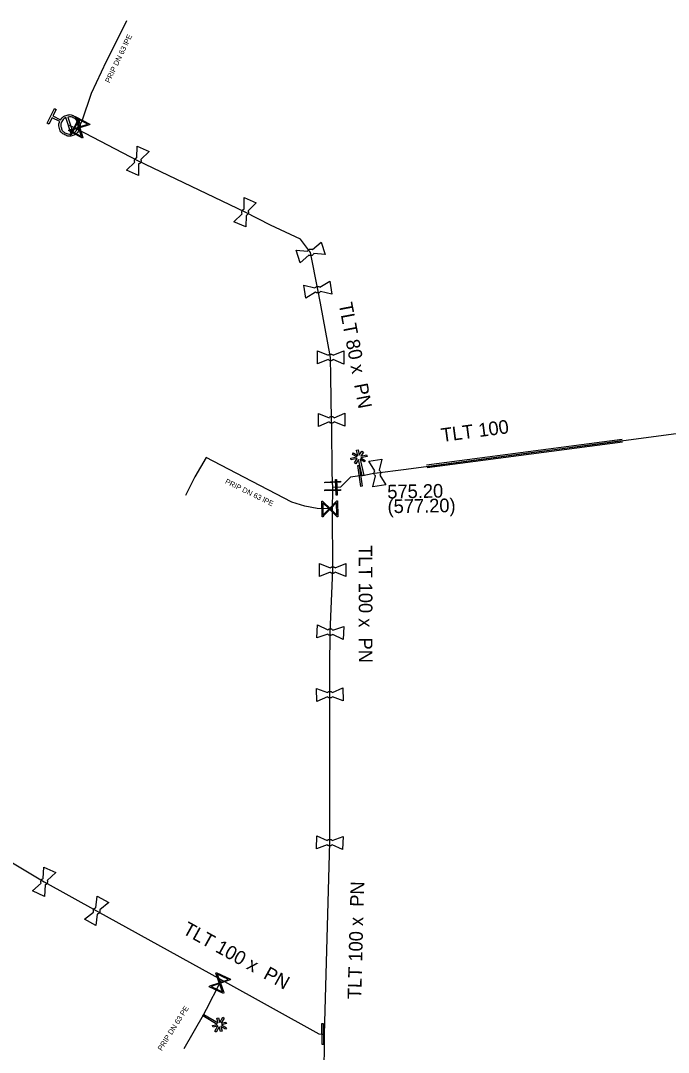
# Model space of a CAD drawing. Extents: x -643842 to -636370, y -1119190 to -1110210.
# Drawn here: x -641967.7 to -641906.1, y -1115301.5 to -1115203.3 of the extents above; entities that cross this region are included whole.
import ezdxf

# ---------------------------------------------------------------- set-up
doc = ezdxf.new("R2010")
doc.units = 0
for name, color, linetype in [('2', 7, 'Continuous'), ('22', 7, 'Continuous'), ('Default', 7, 'Continuous'), ('Level 16', 7, 'Continuous'), ('Level 20', 7, 'Continuous'), ('Level 21', 7, 'Continuous'), ('Level 23', 7, 'Continuous'), ('Level 27', 7, 'Continuous'), ('Level 28', 7, 'Continuous'), ('Level 29', 7, 'Continuous'), ('Level 30', 7, 'Continuous'), ('Level 33', 7, 'Continuous')]:
    doc.layers.add(name, color=color, linetype=linetype)

msp = doc.modelspace()

# ---------------------------------------------------------------- linework, layer by layer
at = {"layer": '2'}
for points in [[(-641935.602, -1115244.661), (-641935.717, -1115244.134), (-641935.565, -1115244.1), (-641935.451, -1115244.623), (-641935.198, -1115244.228), (-641935.067, -1115244.313), (-641935.318, -1115244.705), (-641934.755, -1115244.582), (-641934.721, -1115244.735), (-641935.294, -1115244.86), (-641934.895, -1115245.115), (-641934.978, -1115245.246), (-641935.369, -1115244.996), (-641935.031, -1115246.543), (-641935.184, -1115246.576), (-641935.523, -1115245.025), (-641935.777, -1115245.422), (-641935.908, -1115245.337), (-641935.653, -1115244.938), (-641936.224, -1115245.063), (-641936.257, -1115244.91), (-641935.696, -1115244.787), (-641936.085, -1115244.536), (-641936.002, -1115244.406), (-641935.602, -1115244.661)], [(-641948.558, -1115298.841), (-641948.091, -1115299.112), (-641948.17, -1115299.247), (-641948.632, -1115298.978), (-641948.512, -1115299.431), (-641948.663, -1115299.47), (-641948.782, -1115299.021), (-641949.072, -1115299.519), (-641949.207, -1115299.44), (-641948.913, -1115298.934), (-641949.37, -1115299.056), (-641949.41, -1115298.905), (-641948.962, -1115298.786), (-641950.331, -1115297.99), (-641950.252, -1115297.855), (-641948.879, -1115298.654), (-641949.001, -1115298.197), (-641948.85, -1115298.158), (-641948.728, -1115298.616), (-641948.434, -1115298.111), (-641948.298, -1115298.189), (-641948.588, -1115298.686), (-641948.139, -1115298.569), (-641948.1, -1115298.719), (-641948.558, -1115298.841)]]:
    msp.add_lwpolyline(points, dxfattribs=at)
at = {"layer": 'Default'}
for points in [[(-641963.867, -1115212.699), (-641963.679, -1115212.391), (-641963.331, -1115212.278), (-641962.938, -1115212.151), (-641962.567, -1115212.339), (-641962.197, -1115212.525), (-641962.069, -1115212.919), (-641961.941, -1115213.312), (-641962.129, -1115213.683), (-641962.314, -1115214.051), (-641962.707, -1115214.18), (-641963.1, -1115214.31), (-641963.47, -1115214.123), (-641963.841, -1115213.936), (-641963.971, -1115213.544), (-641964.088, -1115213.195), (-641963.95, -1115212.862)], [(-641963.359, -1115212.489), (-641963.615, -1115212.603), (-641963.748, -1115212.864), (-641963.9, -1115213.166), (-641963.795, -1115213.485), (-641963.691, -1115213.803), (-641963.389, -1115213.956), (-641963.128, -1115214.088), (-641962.854, -1115214.027)], [(-641962.681, -1115213.971), (-641962.428, -1115213.855), (-641962.298, -1115213.598), (-641962.146, -1115213.298), (-641962.25, -1115212.978), (-641962.354, -1115212.658), (-641962.656, -1115212.506), (-641962.914, -1115212.375), (-641963.186, -1115212.433)], [(-641956.813, -1115216.733), (-641956.836, -1115216.685), (-641956.841, -1115216.63), (-641956.849, -1115216.547), (-641956.815, -1115216.472), (-641956.782, -1115216.397), (-641956.712, -1115216.346), (-641956.669, -1115216.314), (-641956.618, -1115216.299)], [(-641956.245, -1115216.467), (-641956.224, -1115216.514), (-641956.218, -1115216.567), (-641956.211, -1115216.653), (-641956.245, -1115216.728), (-641956.278, -1115216.803), (-641956.346, -1115216.852), (-641956.39, -1115216.885), (-641956.441, -1115216.9)], [(-641946.6, -1115221.628), (-641946.624, -1115221.581), (-641946.63, -1115221.526), (-641946.64, -1115221.443), (-641946.607, -1115221.368), (-641946.575, -1115221.292), (-641946.506, -1115221.239), (-641946.465, -1115221.207), (-641946.414, -1115221.191)], [(-641946.038, -1115221.351), (-641946.015, -1115221.398), (-641946.009, -1115221.451), (-641946, -1115221.537), (-641946.033, -1115221.612), (-641946.065, -1115221.688), (-641946.131, -1115221.739), (-641946.175, -1115221.772), (-641946.225, -1115221.788)], [(-641940.369, -1115225.19), (-641940.349, -1115225.141), (-641940.312, -1115225.101), (-641940.255, -1115225.039), (-641940.178, -1115225.013), (-641940.1, -1115224.988), (-641940.015, -1115225.005), (-641939.963, -1115225.014), (-641939.918, -1115225.042)], [(-641939.79, -1115225.431), (-641939.81, -1115225.478), (-641939.846, -1115225.518), (-641939.905, -1115225.581), (-641939.982, -1115225.607), (-641940.06, -1115225.632), (-641940.143, -1115225.616), (-641940.196, -1115225.605), (-641940.241, -1115225.578)], [(-641939.674, -1115228.693), (-641939.646, -1115228.648), (-641939.603, -1115228.615), (-641939.537, -1115228.563), (-641939.456, -1115228.551), (-641939.375, -1115228.539), (-641939.294, -1115228.57), (-641939.244, -1115228.589), (-641939.204, -1115228.623)], [(-641939.144, -1115229.028), (-641939.172, -1115229.072), (-641939.214, -1115229.105), (-641939.283, -1115229.157), (-641939.364, -1115229.169), (-641939.445, -1115229.181), (-641939.524, -1115229.151), (-641939.575, -1115229.131), (-641939.614, -1115229.096)], [(-641937.943, -1115235.516), (-641937.977, -1115235.555), (-641938.024, -1115235.582), (-641938.1, -1115235.623), (-641938.181, -1115235.622), (-641938.263, -1115235.622), (-641938.336, -1115235.58), (-641938.384, -1115235.553), (-641938.418, -1115235.513)], [(-641938.416, -1115235.105), (-641938.381, -1115235.065), (-641938.334, -1115235.038), (-641938.26, -1115234.997), (-641938.179, -1115234.998), (-641938.097, -1115234.998), (-641938.021, -1115235.041), (-641937.975, -1115235.067), (-641937.941, -1115235.107)], [(-641938.328, -1115241.048), (-641938.294, -1115241.007), (-641938.247, -1115240.98), (-641938.174, -1115240.938), (-641938.092, -1115240.938), (-641938.01, -1115240.937), (-641937.934, -1115240.979), (-641937.888, -1115241.004), (-641937.853, -1115241.045)], [(-641937.851, -1115241.453), (-641937.884, -1115241.493), (-641937.931, -1115241.52), (-641938.006, -1115241.562), (-641938.088, -1115241.562), (-641938.17, -1115241.563), (-641938.243, -1115241.522), (-641938.291, -1115241.496), (-641938.325, -1115241.455)], [(-641933.906, -1115246.575), (-641933.951, -1115246.547), (-641933.985, -1115246.504), (-641934.037, -1115246.438), (-641934.049, -1115246.357), (-641934.061, -1115246.276), (-641934.03, -1115246.195), (-641934.012, -1115246.145), (-641933.977, -1115246.105)], [(-641933.573, -1115246.044), (-641933.529, -1115246.072), (-641933.496, -1115246.114), (-641933.443, -1115246.182), (-641933.431, -1115246.263), (-641933.419, -1115246.344), (-641933.449, -1115246.423), (-641933.468, -1115246.474), (-641933.503, -1115246.513)], [(-641938.217, -1115255.346), (-641938.183, -1115255.306), (-641938.135, -1115255.279), (-641938.062, -1115255.238), (-641937.98, -1115255.238), (-641937.898, -1115255.238), (-641937.823, -1115255.28), (-641937.776, -1115255.306), (-641937.742, -1115255.346)], [(-641937.742, -1115255.755), (-641937.776, -1115255.794), (-641937.823, -1115255.821), (-641937.898, -1115255.863), (-641937.98, -1115255.863), (-641938.062, -1115255.863), (-641938.135, -1115255.821), (-641938.183, -1115255.794), (-641938.217, -1115255.754)], [(-641938.433, -1115261.232), (-641938.397, -1115261.194), (-641938.348, -1115261.17), (-641938.272, -1115261.133), (-641938.19, -1115261.138), (-641938.109, -1115261.143), (-641938.036, -1115261.191), (-641937.991, -1115261.219), (-641937.96, -1115261.262)], [(-641937.985, -1115261.67), (-641938.022, -1115261.707), (-641938.07, -1115261.73), (-641938.148, -1115261.767), (-641938.23, -1115261.762), (-641938.311, -1115261.757), (-641938.382, -1115261.711), (-641938.428, -1115261.681), (-641938.459, -1115261.638)], [(-641938.492, -1115267.213), (-641938.459, -1115267.171), (-641938.412, -1115267.143), (-641938.34, -1115267.1), (-641938.258, -1115267.098), (-641938.177, -1115267.095), (-641938.1, -1115267.136), (-641938.053, -1115267.16), (-641938.018, -1115267.2)], [(-641938.007, -1115267.609), (-641938.04, -1115267.649), (-641938.085, -1115267.677), (-641938.16, -1115267.72), (-641938.242, -1115267.722), (-641938.323, -1115267.725), (-641938.398, -1115267.685), (-641938.446, -1115267.66), (-641938.481, -1115267.62)], [(-641938.038, -1115281.702), (-641938.074, -1115281.74), (-641938.121, -1115281.766), (-641938.198, -1115281.805), (-641938.279, -1115281.802), (-641938.361, -1115281.8), (-641938.433, -1115281.756), (-641938.48, -1115281.728), (-641938.513, -1115281.687)], [(-641938.501, -1115281.279), (-641938.465, -1115281.24), (-641938.417, -1115281.214), (-641938.342, -1115281.175), (-641938.261, -1115281.178), (-641938.179, -1115281.18), (-641938.105, -1115281.225), (-641938.059, -1115281.252), (-641938.026, -1115281.293)], [(-641965.715, -1115285.338), (-641965.737, -1115285.29), (-641965.741, -1115285.235), (-641965.748, -1115285.151), (-641965.713, -1115285.077), (-641965.678, -1115285.003), (-641965.607, -1115284.953), (-641965.564, -1115284.922), (-641965.513, -1115284.908)], [(-641965.143, -1115285.082), (-641965.122, -1115285.129), (-641965.118, -1115285.183), (-641965.112, -1115285.269), (-641965.147, -1115285.343), (-641965.182, -1115285.417), (-641965.251, -1115285.465), (-641965.295, -1115285.497), (-641965.346, -1115285.511)], [(-641960.733, -1115288.098), (-641960.752, -1115288.049), (-641960.752, -1115287.994), (-641960.753, -1115287.91), (-641960.713, -1115287.838), (-641960.674, -1115287.767), (-641960.6, -1115287.721), (-641960.555, -1115287.693), (-641960.503, -1115287.683)], [(-641960.145, -1115287.881), (-641960.128, -1115287.93), (-641960.127, -1115287.984), (-641960.127, -1115288.07), (-641960.167, -1115288.142), (-641960.206, -1115288.213), (-641960.278, -1115288.257), (-641960.325, -1115288.286), (-641960.377, -1115288.296)]]:
    msp.add_open_spline(points, degree=3, dxfattribs=at)
at = {"layer": 'Level 16'}
for points in [[(-641962.405, -1115212.404), (-641961.084, -1115213.115), (-641961.115, -1115213.173), (-641961.24, -1115213.206), (-641962.044, -1115213.449), (-641961.764, -1115214.378), (-641961.795, -1115214.436), (-641963.116, -1115213.725), (-641963.085, -1115213.667), (-641962.153, -1115213.39), (-641962.396, -1115212.585), (-641962.436, -1115212.462), (-641962.405, -1115212.404)], [(-641962.183, -1115212.82), (-641962.853, -1115214.162), (-641962.937, -1115214.12), (-641962.267, -1115212.778), (-641962.183, -1115212.82)], [(-641962.311, -1115212.561), (-641962.069, -1115213.364), (-641961.268, -1115213.122), (-641962.311, -1115212.561)], [(-641961.885, -1115214.281), (-641962.128, -1115213.474), (-641962.933, -1115213.717), (-641961.885, -1115214.281)], [(-641935.482, -1115245.592), (-641935.174, -1115247.569), (-641935.298, -1115247.588), (-641935.606, -1115245.611), (-641935.482, -1115245.592)], [(-641938.741, -1115247.167), (-641937.243, -1115247.1), (-641937.239, -1115247.193), (-641938.737, -1115247.26), (-641938.741, -1115247.167)], [(-641937.618, -1115246.929), (-641937.568, -1115248.428), (-641937.662, -1115248.431), (-641937.712, -1115246.932), (-641937.618, -1115246.929)], [(-641938.731, -1115247.914), (-641937.232, -1115247.872), (-641937.229, -1115247.966), (-641938.728, -1115248.008), (-641938.731, -1115247.914)], [(-641938.999, -1115250.491), (-641939.021, -1115248.991), (-641938.955, -1115248.99), (-641938.866, -1115249.083), (-641938.262, -1115249.667), (-641937.587, -1115248.97), (-641937.521, -1115248.969), (-641937.499, -1115250.469), (-641937.565, -1115250.47), (-641938.261, -1115249.792), (-641938.845, -1115250.395), (-641938.933, -1115250.49), (-641938.999, -1115250.491)], [(-641938.907, -1115250.332), (-641938.324, -1115249.73), (-641938.925, -1115249.148), (-641938.907, -1115250.332)], [(-641937.613, -1115249.122), (-641938.199, -1115249.728), (-641937.595, -1115250.313), (-641937.613, -1115249.122)], [(-641948.367, -1115295.85), (-641949.72, -1115295.203), (-641949.692, -1115295.143), (-641949.569, -1115295.104), (-641948.777, -1115294.824), (-641949.101, -1115293.909), (-641949.073, -1115293.85), (-641947.72, -1115294.497), (-641947.748, -1115294.557), (-641948.665, -1115294.878), (-641948.385, -1115295.67), (-641948.339, -1115295.791), (-641948.367, -1115295.85)], [(-641948.976, -1115294), (-641948.694, -1115294.795), (-641947.901, -1115294.514), (-641948.976, -1115294)], [(-641948.469, -1115295.698), (-641948.748, -1115294.907), (-641949.537, -1115295.186), (-641948.469, -1115295.698)], [(-641938.894, -1115298.709), (-641938.862, -1115300.709), (-641938.986, -1115300.711), (-641939.018, -1115298.711), (-641938.894, -1115298.709)]]:
    msp.add_lwpolyline(points, dxfattribs=at)
at = {"layer": 'Level 21'}
for points in [[(-641937.98, -1115247.67), (-641937.99, -1115247.18), (-641938.02, -1115246.12), (-641938.07, -1115242), (-641938.09, -1115241.25), (-641938.15, -1115237.17), (-641938.18, -1115235.31), (-641939.16, -1115230.16), (-641939.41, -1115228.86), (-641940.08, -1115225.31), (-641941.05, -1115224.07), (-641943.91, -1115222.73), (-641946.32, -1115221.49), (-641956.53, -1115216.6), (-641962.23, -1115213.63), (-641962.56, -1115213.47), (-641963.02, -1115213.23)], [(-641935.11, -1115246.56), (-641934.24, -1115246.37), (-641933.74, -1115246.31), (-641931.25, -1115245.98), (-641925.3, -1115245.19), (-641919.35, -1115244.4), (-641913.41, -1115243.62), (-641907.46, -1115242.83), (-641901.51, -1115242.05)], [(-641935.11, -1115246.56), (-641935.39, -1115246.59), (-641936.29, -1115246.7), (-641937.25, -1115247.66), (-641937.64, -1115247.68), (-641937.98, -1115247.67)], [(-641938.75, -1115299.71), (-641938.27, -1115281.49), (-641938.25, -1115269.65), (-641938.25, -1115267.41), (-641938.25, -1115264.85), (-641938.21, -1115261.45), (-641937.98, -1115255.55), (-641937.99, -1115249.72), (-641937.98, -1115247.94), (-641937.98, -1115247.67)], [(-642013.72, -1115256.17), (-642013.66, -1115256.58), (-642013.59, -1115257), (-642011.72, -1115258.22), (-642004.55, -1115262.55), (-641998.5, -1115265.99), (-641989.91, -1115270.78), (-641986.24, -1115273.14), (-641982.43, -1115275.1), (-641977.98, -1115277.64), (-641973.33, -1115280.49), (-641965.43, -1115285.21), (-641960.44, -1115287.99), (-641948.57, -1115294.56), (-641939.29, -1115299.7), (-641938.94, -1115299.71), (-641938.75, -1115299.71)], [(-641939.2, -1115380.32), (-641938.99, -1115374.57), (-641939.38, -1115365.52), (-641939.48, -1115362.58), (-641939.69, -1115357.26), (-641939.22, -1115339.3), (-641939.09, -1115331.09), (-641938.89, -1115318.23), (-641938.86, -1115315.16), (-641938.84, -1115314.08), (-641938.78, -1115304.09), (-641938.75, -1115299.71)]]:
    msp.add_lwpolyline(points, dxfattribs=at)
at = {"layer": 'Level 23'}
for points in [[(-641962.23, -1115213.63), (-641961.8, -1115212.79), (-641960.93, -1115210.15), (-641959.5, -1115207.1), (-641958.46, -1115205.05), (-641957.578, -1115203.255)], [(-641937.99, -1115249.72), (-641938.1, -1115249.72), (-641938.26, -1115249.73), (-641939.45, -1115249.68), (-641940.63, -1115249.47), (-641941.86, -1115249.08), (-641947.88, -1115245.94), (-641950.01, -1115244.82), (-641951.09, -1115246.67), (-641951.984, -1115248.459)], [(-641948.57, -1115294.56), (-641948.72, -1115294.85), (-641950.01, -1115297.36), (-641950.29, -1115297.92)], [(-641950.29, -1115297.92), (-641952.149, -1115301.114)]]:
    msp.add_lwpolyline(points, dxfattribs=at)
at = {"layer": 'Level 28'}
for points in [[(-641956.618, -1115216.299), (-641956.588, -1115215.204)], [(-641956.588, -1115215.204), (-641955.448, -1115215.716), (-641956.245, -1115216.467)], [(-641956.441, -1115216.9), (-641956.472, -1115217.996), (-641957.612, -1115217.484), (-641956.813, -1115216.733)], [(-641946.414, -1115221.191), (-641946.405, -1115220.095)], [(-641946.405, -1115220.095), (-641945.255, -1115220.585), (-641946.038, -1115221.351)], [(-641946.225, -1115221.788), (-641946.235, -1115222.885), (-641947.385, -1115222.395), (-641946.6, -1115221.628)], [(-641939.918, -1115225.042), (-641939.088, -1115224.326)], [(-641939.088, -1115224.326), (-641938.697, -1115225.514), (-641939.79, -1115225.431)], [(-641940.241, -1115225.578), (-641941.072, -1115226.294), (-641941.463, -1115225.106), (-641940.369, -1115225.19)], [(-641939.614, -1115229.096), (-641940.555, -1115229.662), (-641940.738, -1115228.425), (-641939.674, -1115228.693)], [(-641939.204, -1115228.623), (-641938.265, -1115228.058)], [(-641938.265, -1115228.058), (-641938.082, -1115229.295), (-641939.144, -1115229.028)], [(-641938.418, -1115235.513), (-641939.433, -1115235.929), (-641939.427, -1115234.679), (-641938.416, -1115235.105)], [(-641936.927, -1115234.691), (-641936.933, -1115235.941), (-641937.943, -1115235.516)], [(-641937.941, -1115235.107), (-641936.927, -1115234.691)], [(-641938.325, -1115241.455), (-641939.336, -1115241.884), (-641939.344, -1115240.634), (-641938.328, -1115241.048)], [(-641937.853, -1115241.045), (-641936.844, -1115240.616)], [(-641936.844, -1115240.616), (-641936.836, -1115241.866), (-641937.851, -1115241.453)], [(-641934.546, -1115245.168), (-641933.31, -1115244.98), (-641933.573, -1115246.044)], [(-641933.977, -1115246.105), (-641934.546, -1115245.168)], [(-641933.503, -1115246.513), (-641932.934, -1115247.452), (-641934.17, -1115247.64), (-641933.906, -1115246.575)], [(-641938.217, -1115255.754), (-641939.23, -1115256.175), (-641939.23, -1115254.925), (-641938.217, -1115255.346)], [(-641936.73, -1115254.925), (-641936.73, -1115256.175), (-641937.742, -1115255.755)], [(-641937.742, -1115255.346), (-641936.73, -1115254.925)], [(-641938.459, -1115261.638), (-641939.497, -1115261.995), (-641939.418, -1115260.747), (-641938.433, -1115261.232)], [(-641936.923, -1115260.905), (-641937.002, -1115262.153), (-641937.985, -1115261.67)], [(-641937.96, -1115261.262), (-641936.923, -1115260.905)], [(-641938.481, -1115267.62), (-641939.483, -1115268.068), (-641939.516, -1115266.819), (-641938.492, -1115267.213)], [(-641938.018, -1115267.2), (-641937.017, -1115266.752)], [(-641937.017, -1115266.752), (-641936.984, -1115268.001), (-641938.007, -1115267.609)], [(-641938.513, -1115281.687), (-641939.538, -1115282.077), (-641939.501, -1115280.828), (-641938.501, -1115281.279)], [(-641937.002, -1115280.903), (-641937.039, -1115282.152), (-641938.038, -1115281.702)], [(-641938.026, -1115281.293), (-641937.002, -1115280.903)], [(-641965.513, -1115284.908), (-641965.465, -1115283.813)], [(-641965.465, -1115283.813), (-641964.333, -1115284.344), (-641965.143, -1115285.082)], [(-641965.346, -1115285.511), (-641965.395, -1115286.607), (-641966.527, -1115286.076), (-641965.715, -1115285.338)], [(-641960.503, -1115287.683), (-641960.38, -1115286.594)], [(-641960.38, -1115286.594), (-641959.287, -1115287.2), (-641960.145, -1115287.881)], [(-641960.377, -1115288.296), (-641960.5, -1115289.386), (-641961.593, -1115288.78), (-641960.733, -1115288.098)]]:
    msp.add_lwpolyline(points, dxfattribs=at)
at = {"layer": 'Level 29'}
for points in [[(-641929.048, -1115245.541), (-641910.453, -1115243.086)], [(-641910.417, -1115243.364), (-641929.012, -1115245.819)]]:
    msp.add_lwpolyline(points, dxfattribs=at)
at = {"layer": 'Level 30'}
msp.add_lwpolyline([(-641929.03, -1115245.68), (-641910.435, -1115243.225)], dxfattribs=at)
at = {"layer": 'Level 33'}
for points in [[(-641963.95, -1115212.862), (-641964.682, -1115212.492), (-641964.993, -1115213.107), (-641965.157, -1115213.025), (-641964.452, -1115211.63), (-641964.288, -1115211.713), (-641964.599, -1115212.328), (-641963.867, -1115212.699)], [(-641962.854, -1115214.027), (-641963.359, -1115212.489)], [(-641963.186, -1115212.433), (-641962.681, -1115213.971)]]:
    msp.add_lwpolyline(points, dxfattribs=at)

# ---------------------------------------------------------------- texts
at = {"layer": '22'}
for s, rotation, p in [('PRIP DN 63 lPE', 64.3329, (-641959.216, -1115209.23)), ('PRIP DN 63 lPE', 333.8244, (-641948.272, -1115247.276)), ('PRIP DN 63 PE', 57.61784, (-641954.253, -1115301.351))]:
    msp.add_text(s, height=0.5, rotation=rotation, dxfattribs=at).set_placement(p)
at = {"layer": 'Level 20'}
for s, rotation, p in [('TLT 80 x  PN ', 280.77407, (-641937.418, -1115230.204)), ('TLT 100', 7.5631, (-641927.584, -1115243.364)), ('TLT 100 x  PN ', 270.09828, (-641935.516, -1115253.176)), ('TLT 100 x  PN ', 88.49091, (-641935.274, -1115296.401)), ('TLT 100 x  PN ', 331.03564, (-641952.359, -1115290.096))]:
    msp.add_text(s, height=1.3, rotation=rotation, dxfattribs=at).set_placement(p)
at = {"layer": 'Level 27'}
for s, p in [('575.20', (-641932.781, -1115248.741)), ('(577.20)', (-641932.757, -1115250.14))]:
    msp.add_text(s, height=1.3, rotation=1, dxfattribs=at).set_placement(p)

doc.saveas('drawing.dxf')
